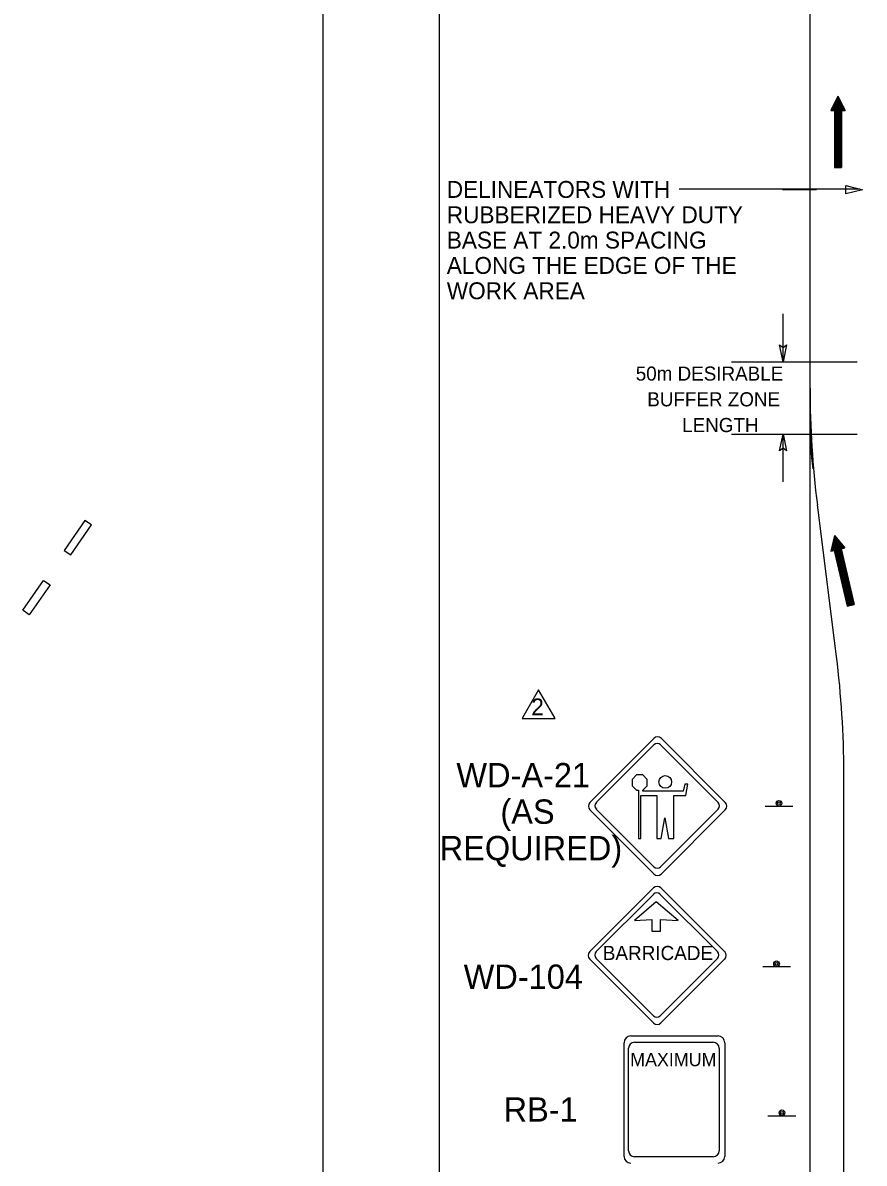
# Model space of a CAD drawing. Extents: x 2157 to 2399, y 147 to 426.
# Drawn here: x 2156.9 to 2229.2, y 269.5 to 367.4 of the extents above; entities that cross this region are included whole.
import ezdxf

# ---------------------------------------------------------------- set-up
doc = ezdxf.new("R2010")
doc.units = 0
for name, color, linetype in [('Level 1', 7, 'Continuous'), ('Level 10', 7, 'Continuous'), ('Level 29', 7, 'Continuous'), ('Level 44', 7, 'Continuous'), ('Level 5', 7, 'Continuous'), ('Level 60', 7, 'Continuous'), ('Level 62', 7, 'Continuous')]:
    doc.layers.add(name, color=color, linetype=linetype)

# ---------------------------------------------------------------- blocks, each defined once
blk = doc.blocks.new('LT1')
at = {"layer": 'Level 5'}
blk.add_lwpolyline([(0, 0), (-3, -0.62), (-2.504, 0), (-3, 0.62)], close=True, dxfattribs=at)
blk = doc.blocks.new('APRNTR')
at = {"layer": 'Level 60'}
for points in [[(19.126, 268.191), (-196.874, 268.191), (-196.874, -10.809), (19.126, -10.809)], [(0, 257.382), (-186.874, 257.382), (-186.874, 0), (0, 0)]]:
    blk.add_lwpolyline(points, close=True, dxfattribs=at)

msp = doc.modelspace()

# ---------------------------------------------------------------- linework, layer by layer
at = {"layer": 'Level 1'}
for p, q in [((2228.904, 353.142), (2213.347, 353.142)), ((2209.678, 302.825), (2209.295, 302.442)), ((2210.221, 302.825), (2209.678, 302.825)), ((2210.604, 302.442), (2210.221, 302.825)), ((2209.295, 302.442), (2209.295, 301.899)), ((2209.295, 301.899), (2209.678, 301.516)), ((2210.221, 301.516), (2210.604, 301.899)), ((2210.604, 301.899), (2210.604, 302.442)), ((2213.837, 302.028), (2213.697, 301.445)), ((2214.081, 302.028), (2213.837, 302.028)), ((2213.922, 301.054), (2214.081, 302.028)), ((2209.678, 301.516), (2209.852, 301.516)), ((2209.852, 301.516), (2209.852, 297.362)), ((2210.042, 297.362), (2210.042, 301.054)), ((2210.042, 301.054), (2211.425, 301.054)), ((2210.221, 301.445), (2210.221, 301.516)), ((2213.697, 301.445), (2210.221, 301.445)), ((2211.425, 301.054), (2211.425, 297.362)), ((2212.874, 297.362), (2212.874, 301.054)), ((2212.874, 301.054), (2213.922, 301.054)), ((2211.792, 297.362), (2212.119, 299.131)), ((2212.119, 299.131), (2212.428, 297.362)), ((2209.852, 297.362), (2210.042, 297.362)), ((2211.425, 297.362), (2211.792, 297.362)), ((2212.428, 297.362), (2212.874, 297.362))]:
    msp.add_line(p, q, dxfattribs=at)
msp.add_lwpolyline([(2227.673, 353.454), (2229.113, 353.094), (2227.673, 352.734)], close=True, dxfattribs=at)
msp.add_circle((2212.154, 302.223), 0.544, dxfattribs=at)
at = {"layer": 'Level 10'}
for p, q in [((2224.589, 366.459), (2224.589, 369.836)), ((2224.589, 338.668), (2224.589, 366.459)), ((2226.992, 361.139), (2226.378, 359.912)), ((2226.686, 360.526), (2226.686, 355.003)), ((2226.762, 360.678), (2226.762, 355.003)), ((2226.838, 360.832), (2226.838, 355.003)), ((2226.916, 360.985), (2226.916, 355.003)), ((2226.992, 361.139), (2226.992, 355.003)), ((2226.992, 361.139), (2227.605, 359.912)), ((2227.068, 360.985), (2227.068, 355.003)), ((2227.145, 360.832), (2227.145, 355.003)), ((2227.222, 360.678), (2227.222, 355.003)), ((2227.299, 360.526), (2227.299, 355.003)), ((2226.378, 359.912), (2226.686, 359.912)), ((2226.455, 360.065), (2226.455, 359.912)), ((2226.531, 360.219), (2226.531, 359.912)), ((2226.608, 360.372), (2226.608, 359.912)), ((2226.686, 359.912), (2226.686, 355.003)), ((2227.299, 359.912), (2227.299, 355.003)), ((2227.299, 359.912), (2227.605, 359.912)), ((2227.376, 360.372), (2227.376, 359.912)), ((2227.452, 360.219), (2227.452, 359.912)), ((2227.529, 360.065), (2227.529, 359.912)), ((2226.686, 355.003), (2227.299, 355.003)), ((2222.231, 353.123), (2225.133, 353.123)), ((2222.269, 338.325), (2222.269, 342.441)), ((2224.589, 336.036), (2224.589, 339.179)), ((2217.854, 338.325), (2228.631, 338.325)), ((2224.589, 200.123), (2224.589, 338.668)), ((2217.854, 332.112), (2228.631, 332.112)), ((2222.269, 327.997), (2222.269, 332.112)), ((2226.862, 313.006), (2225.22, 326.014)), ((2226.695, 323.381), (2226.373, 322.047)), ((2226.695, 323.381), (2228.075, 317.403)), ((2226.695, 323.381), (2227.568, 322.323)), ((2226.452, 322.381), (2226.522, 322.081)), ((2226.493, 322.547), (2226.597, 322.099)), ((2226.534, 322.714), (2227.776, 317.334)), ((2226.574, 322.88), (2227.85, 317.351)), ((2226.613, 323.047), (2227.924, 317.368)), ((2226.655, 323.214), (2228.001, 317.386)), ((2226.803, 323.248), (2228.149, 317.42)), ((2226.913, 323.116), (2228.224, 317.437)), ((2227.022, 322.983), (2228.299, 317.454)), ((2227.131, 322.852), (2228.373, 317.472)), ((2227.24, 322.72), (2227.344, 322.271)), ((2227.269, 322.255), (2227.568, 322.323)), ((2227.349, 322.588), (2227.419, 322.288)), ((2227.459, 322.455), (2227.494, 322.306)), ((2226.373, 322.047), (2226.672, 322.116)), ((2226.413, 322.213), (2226.448, 322.065)), ((2226.672, 322.116), (2227.776, 317.334)), ((2227.269, 322.255), (2228.373, 317.472)), ((2227.776, 317.334), (2228.373, 317.472)), ((2227.492, 236.238), (2227.492, 302.984))]:
    msp.add_line(p, q, dxfattribs=at)
for centre, radius, start, end in [((2304.589, 336.036), 80, 180, 187.19647), ((2254.589, 332.892), 30, 180, 187.19647), ((2147.492, 302.984), 80, 0, 7.19647)]:
    msp.add_arc(centre, radius, start, end, dxfattribs=at)
at = {"layer": 'Level 29'}
for points in [[(2201.269, 310.147), (2199.876, 307.722)], [(2202.662, 307.72), (2201.268, 310.145)], [(2199.876, 307.722), (2199.85, 307.677), (2202.689, 307.677), (2202.663, 307.722)]]:
    msp.add_lwpolyline(points, dxfattribs=at)
at = {"layer": 'Level 44'}
for p, q in [((2211.17, 305.954), (2205.676, 300.468)), ((2217.304, 300.468), (2211.819, 305.954)), ((2206.226, 300.464), (2211.17, 305.401)), ((2211.754, 305.401), (2216.692, 300.464)), ((2205.676, 299.817), (2211.17, 294.326)), ((2205.681, 299.817), (2205.676, 299.817)), ((2211.17, 294.937), (2206.226, 299.877)), ((2216.692, 299.877), (2211.754, 294.937)), ((2211.819, 294.326), (2217.304, 299.817)), ((2223.122, 300.124), (2220.726, 300.124)), ((2211.136, 293.119), (2205.658, 287.65)), ((2217.252, 287.65), (2211.783, 293.119)), ((2206.206, 287.645), (2211.136, 292.568)), ((2211.718, 292.568), (2216.642, 287.645)), ((2211.377, 291.922), (2209.495, 290.335)), ((2213.259, 290.335), (2211.377, 291.922)), ((2209.495, 290.335), (2210.999, 290.416)), ((2210.999, 290.416), (2210.999, 289.412)), ((2211.754, 289.412), (2211.754, 290.416)), ((2211.754, 290.416), (2213.259, 290.335)), ((2210.999, 289.412), (2211.749, 289.412)), ((2211.136, 282.134), (2206.206, 287.061)), ((2216.642, 287.061), (2211.718, 282.134)), ((2205.658, 287), (2211.136, 281.525)), ((2205.663, 287), (2205.658, 287)), ((2211.783, 281.525), (2217.252, 287)), ((2222.918, 286.334), (2220.521, 286.334)), ((2209.187, 280.403), (2216.683, 280.403)), ((2208.609, 270.054), (2208.609, 279.824)), ((2208.995, 270.548), (2208.995, 279.343)), ((2209.515, 279.864), (2216.261, 279.864)), ((2216.782, 279.343), (2216.782, 270.548)), ((2217.262, 279.824), (2217.262, 270.054)), ((2220.975, 273.539), (2223.372, 273.539)), ((2208.995, 270.547), (2208.995, 270.548)), ((2208.609, 270.051), (2208.609, 270.054)), ((2216.261, 270.027), (2209.515, 270.027))]:
    msp.add_line(p, q, dxfattribs=at)
for centre, radius in [((2221.919, 300.393), 0.24), ((2221.919, 300.393), 0.12), ((2221.714, 286.603), 0.24), ((2221.714, 286.603), 0.12), ((2222.179, 273.808), 0.24), ((2222.179, 273.808), 0.12)]:
    msp.add_circle(centre, radius, dxfattribs=at)
for centre, radius, start, end in [((2211.493, 305.631), 0.459, 45, 135), ((2211.461, 305.11), 0.413, 45, 135), ((2206.005, 300.142), 0.459, 135, 224.99999), ((2206.521, 300.17), 0.413, 135, 224.99999), ((2216.401, 300.17), 0.413, 315, 45), ((2216.982, 300.142), 0.459, 315, 45), ((2211.461, 295.231), 0.413, 225, 315), ((2211.493, 294.654), 0.459, 225, 315), ((2211.458, 292.797), 0.458, 45, 135), ((2211.426, 292.278), 0.412, 45, 135), ((2205.986, 287.325), 0.458, 135, 224.99999), ((2206.501, 287.353), 0.412, 135, 224.99999), ((2216.351, 287.353), 0.412, 315, 45), ((2216.931, 287.325), 0.458, 315, 45), ((2211.426, 282.427), 0.412, 225, 315), ((2211.458, 281.852), 0.458, 225, 315), ((2209.187, 279.824), 0.578, 90, 179.99999), ((2216.683, 279.824), 0.578, 359.99999, 89.99999), ((2209.515, 279.342), 0.52, 90, 179.99999), ((2216.261, 279.342), 0.52, 359.99999, 89.99999), ((2209.515, 270.547), 0.52, 180, 269.99999), ((2216.261, 270.547), 0.52, 270, 359.99999), ((2209.187, 270.052), 0.578, 180, 269.99999), ((2216.683, 270.052), 0.578, 270, 359.99999)]:
    msp.add_arc(centre, radius, start, end, dxfattribs=at)
at = {"layer": 'Level 62'}
for p, q in [((2162.28, 324.687), (2160.501, 322.114)), ((2161.059, 321.728), (2162.838, 324.302)), ((2162.838, 324.302), (2162.28, 324.687)), ((2160.501, 322.114), (2161.059, 321.728)), ((2156.943, 316.968), (2158.722, 319.541)), ((2158.722, 319.541), (2159.28, 319.155)), ((2159.28, 319.155), (2157.501, 316.582)), ((2157.501, 316.582), (2156.943, 316.968))]:
    msp.add_line(p, q, dxfattribs=at)

# ---------------------------------------------------------------- block references
at = {"layer": 'Level 10'}
msp.add_blockref('APRNTR', (2379.594, 157.795), dxfattribs=at)
at = {"layer": 'Level 5', "xscale": 0.4838, "yscale": 0.4838}
for p, rotation in [((2222.269, 338.325), -90), ((2222.269, 332.112), 90)]:
    msp.add_blockref('LT1', p, dxfattribs=dict(at, rotation=rotation))

# ---------------------------------------------------------------- texts
at = {"layer": 'Level 10'}
for s, height, p in [('DELINEATORS WITH ', 1.451, (2193.378, 352.397)), ('RUBBERIZED HEAVY DUTY ', 1.451, (2193.378, 350.221)), ('BASE AT 2.0m SPACING ', 1.451, (2193.378, 348.045)), ('ALONG THE EDGE OF THE ', 1.451, (2193.378, 345.869)), ('WORK AREA', 1.451, (2193.378, 343.693)), ('WD-A-21', 2.09, (2194.199, 301.763)), ('(AS ', 2.09, (2197.984, 298.629)), ('REQUIRED)', 2.09, (2192.767, 295.495)), ('WD-104', 2.09, (2194.825, 284.45)), ('RB-1', 2.09, (2198.257, 273.044))]:
    msp.add_text(s, height=height, dxfattribs=at).set_placement(p)
msp.add_text('2', height=1.448, rotation=360, dxfattribs=at).set_placement((2200.642, 307.946))
at = {"layer": 'Level 44'}
for s, p in [('50m DESIRABLE', (2209.614, 336.698)), ('BUFFER ZONE', (2210.605, 334.488)), ('LENGTH', (2213.604, 332.279))]:
    msp.add_text(s, height=1.2095, dxfattribs=at).set_placement(p)
for s, height, p in [('BARRICADE', 1.2144, (2206.783, 286.924)), ('MAXIMUM', 1.1467, (2209.136, 277.805))]:
    msp.add_text(s, height=height, rotation=360, dxfattribs=at).set_placement(p)

doc.saveas('drawing.dxf')
